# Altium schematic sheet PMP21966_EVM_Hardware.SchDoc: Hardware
size 431 x 279 mm; Date: Not shown in title block; ApprovedBy: Not shown in title block; CheckedBy: Not shown in title block; Author: Not shown in title block; CompanyName: Not shown in title block; DrawnBy: Tiger Z; Engineer: Not shown in title block; Organization: Not shown in title block; Address1: Not shown in title block; Address2: Not shown in title block; Address3: Not shown in title block; Address4: Not shown in title block; DocumentNumber: 6; Revision: Use project parameter SCH_Rev; SheetNumber: 3; SheetTotal: 3; PageSetup: Record=PageOptions¦CenterHorizontal=True¦CenterVertical=True¦PrintScale=1.00¦XCorrection=1.00¦YCorrection=1.00¦PrintKind=0¦BorderSize=5000000¦LeftOffset=0¦BottomOffset=0¦Orientation=2¦PaperLength=1000¦PaperWidth=1000¦Scale=100¦PaperSource=15¦PrintQuality=600¦MediaType=1¦DitherType=10¦PaperKind=Letter¦PrintScaleMode=1
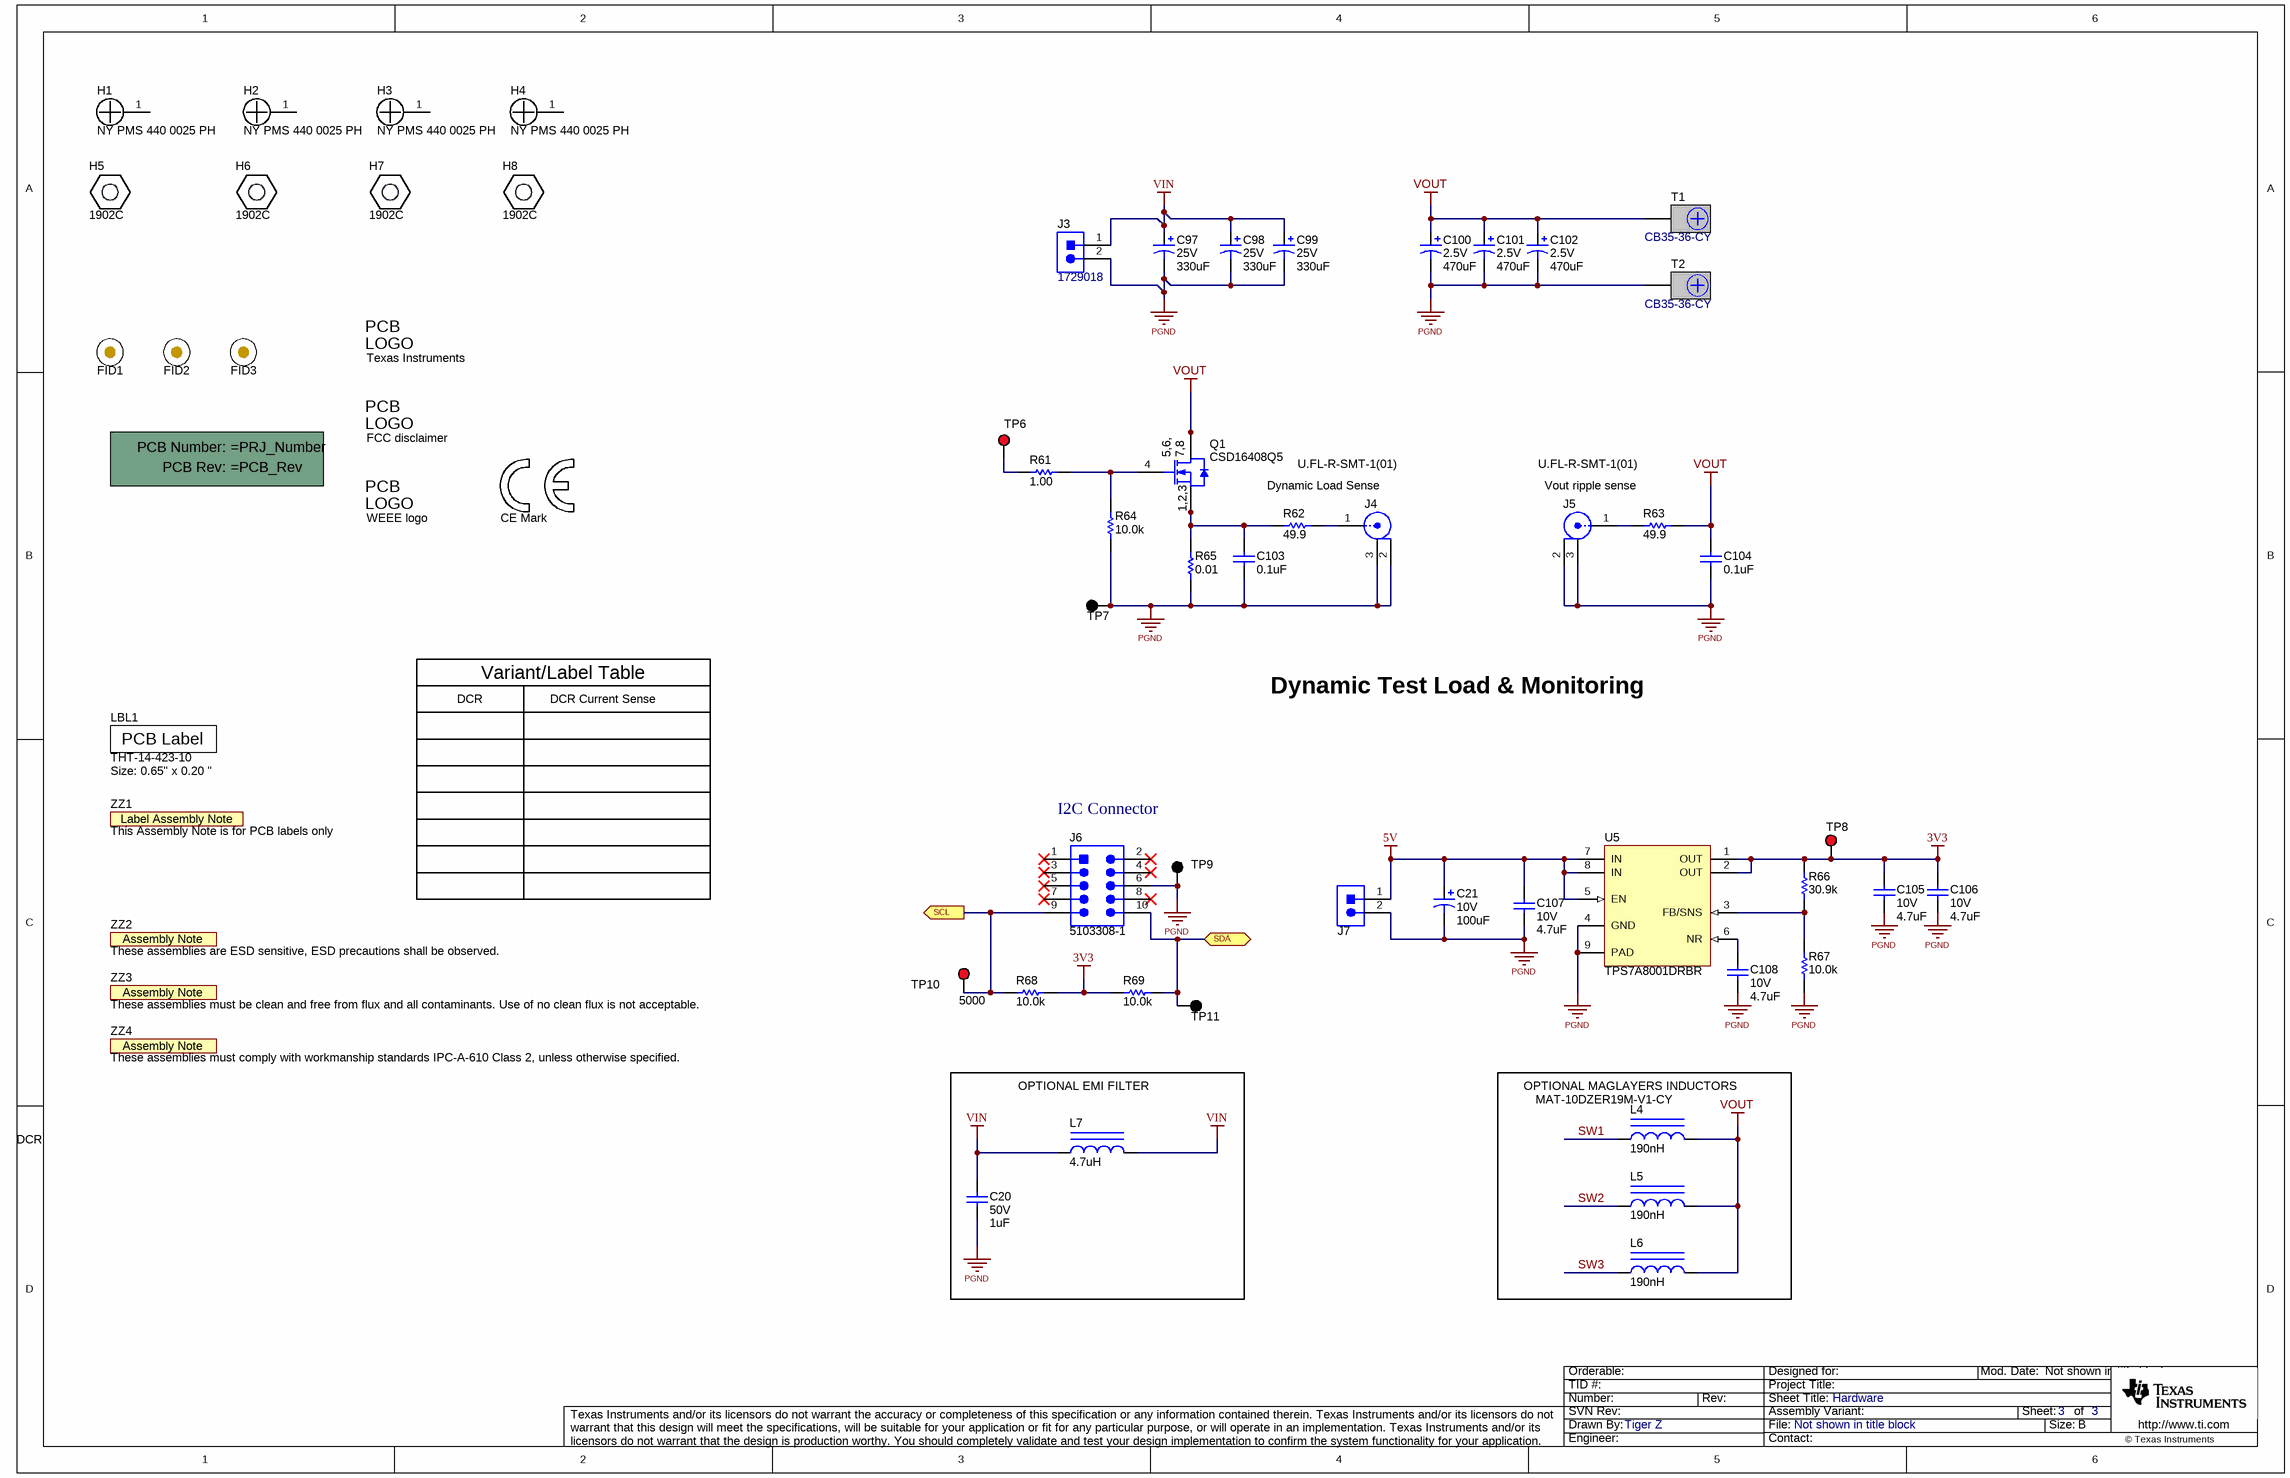
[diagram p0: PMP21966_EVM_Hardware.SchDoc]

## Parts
!PCB1  Printed Circuit Board  (value not drawn)  (mechanical)
C20  VDC_V: 50V  ValueDisplayed: 1uF  [0805_HV]  (hidden comment: C0805C105K5RACTU)
C21  VDC_V: 10V  ValueDisplayed: 100uF  [SM_RADIAL_6.3AMM]  (hidden comment: UUD1A101MCL1GS)
C97  VDC_V: 25V  ValueDisplayed: 330uF  [CAPSMT_62_HA0]  (hidden comment: EMVY250ADA331MHA0G)
C98  VDC_V: 25V  ValueDisplayed: 330uF  [CAPSMT_62_HA0]  (hidden comment: EMVY250ADA331MHA0G)
C99  VDC_V: 25V  ValueDisplayed: 330uF  [CAPSMT_62_HA0]  (hidden comment: EMVY250ADA331MHA0G)
C100  VDC_V: 2.5V  ValueDisplayed: 470uF  [GX_2TERM]  (hidden comment: EEF-GX0E471R)
C101  VDC_V: 2.5V  ValueDisplayed: 470uF  [GX_2TERM]  (hidden comment: EEF-GX0E471R)
C102  VDC_V: 2.5V  ValueDisplayed: 470uF  [GX_2TERM]  (hidden comment: EEF-GX0E471R)
C103  ValueDisplayed: 0.1uF  [0402S]  (hidden comment: CGA2B3X7R1H104K050BB)
C104  ValueDisplayed: 0.1uF  [0402S]  (hidden comment: CGA2B3X7R1H104K050BB)
C105  VDC_V: 10V  ValueDisplayed: 4.7uF  [0603S]  (hidden comment: GRM188Z71A475ME15D)
C106  VDC_V: 10V  ValueDisplayed: 4.7uF  [0603S]  (hidden comment: GRM188Z71A475ME15D)
C107  VDC_V: 10V  ValueDisplayed: 4.7uF  [0603S]  (hidden comment: GRM188Z71A475ME15D)
C108  VDC_V: 10V  ValueDisplayed: 4.7uF  [0603S]  (hidden comment: GRM188Z71A475ME15D)
FID1  Fiducial  [Fiducial10-20]  (value not drawn)
FID2  Fiducial  [Fiducial10-20]  (value not drawn)
FID3  Fiducial  [Fiducial10-20]  (value not drawn)
H1  NY PMS 440 0025 PH  [NY PMS 440 0025 PH]
H2  NY PMS 440 0025 PH  [NY PMS 440 0025 PH]
H3  NY PMS 440 0025 PH  [NY PMS 440 0025 PH]
H4  NY PMS 440 0025 PH  [NY PMS 440 0025 PH]
H5  1902C  [Keystone_1902C]
H6  1902C  [Keystone_1902C]
H7  1902C  [Keystone_1902C]
H8  1902C  [Keystone_1902C]
J3  1729018  [Phoenix_1729018]
J4  U.FL-R-SMT-1(01)  [CONN_UFL-R-SMT-1]
J5  U.FL-R-SMT-1(01)  [CONN_UFL-R-SMT-1]
J6  5103308-1  [CONN_5103308-1]
J7  HTSW-102-07-G-S  [Samtec_HTSW-102-07-G-S]  (value not drawn)
L4  ValueDisplayed: 190nH  [IHLP-4040DZ]  (hidden comment: IHLP4040DZERR19M11)
L5  ValueDisplayed: 190nH  [IHLP-4040DZ]  (hidden comment: IHLP4040DZERR19M11)
L6  ValueDisplayed: 190nH  [IHLP-4040DZ]  (hidden comment: IHLP4040DZERR19M11)
L7  ValueDisplayed: 4.7uH  [IHLP-2525AH]  (hidden comment: IHLP2525AHER4R7M01)
LBL1  THT-14-423-10  Note: Size: 0.65" x 0.20 "  [Label_650x200]
Logo1  Texas Instruments  [TI_Stacked_Overlay_Small]  (no BOM)
Logo2  FCC disclaimer  [FCC_disclaimer]  (no BOM)
Logo3  CE Mark  [CE_Mark_5mm]  (no BOM)
Logo4  WEEE logo  [WEEE_Minimum]  (no BOM)
Q1  CSD16408Q5  [DQH0008A]
R61  ValueDisplayed: 1.00  [0402S]  (hidden comment: CRCW04021R00FKED)
R62  ValueDisplayed: 49.9  [0402S]  (hidden comment: Resistor)
R63  ValueDisplayed: 49.9  [0402S]  (hidden comment: Resistor)
R64  ValueDisplayed: 10.0k  [0402S]  (hidden comment: CRCW040210K0FKED)
R65  ValueDisplayed: 0.01  [2010]  (hidden comment: CSRN2010FK10L0)
R66  ValueDisplayed: 30.9k  [0402S]  (hidden comment: CRCW040230K9FKED)
R67  ValueDisplayed: 10.0k  [0402S]  (hidden comment: CRCW040210K0FKED)
R68  ValueDisplayed: 10.0k  [0402S]  (hidden comment: CRCW040210K0FKED)
R69  ValueDisplayed: 10.0k  [0402S]  (hidden comment: CRCW040210K0FKED)
T1  CB35-36-CY  [CB35-36-CY]
T2  CB35-36-CY  [CB35-36-CY]
TP6  5000  [Keystone5000]  (value not drawn)
TP7  5001  [Keystone5001]  (value not drawn)
TP8  5000  [Keystone5000]  (value not drawn)
TP9  5001  [Keystone5001]  (value not drawn)
TP10  5000  [Keystone5000]
TP11  5001  [Keystone5001]  (value not drawn)
U5  TPS7A8001DRBR  [DRB0008A]
ZZ1  This Assembly Note is for PCB labels only  [AssemblyNoteLabel]  (no BOM)
ZZ2  These assemblies are ESD sensitive, ESD precautions shall be observed.  [AssemblyNote]  (no BOM)
ZZ3  These assemblies must be clean and free from flux and all contaminants. Use of no clean flux is not acceptable.  [AssemblyNote]  (no BOM)
ZZ4  These assemblies must comply with workmanship standards IPC-A-610 Class 2, unless otherwise specified.  [AssemblyNote]  (no BOM)

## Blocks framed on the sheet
OPTIONAL EMI FILTER: C20 L7

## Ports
SCL (out), SDA (bidir)

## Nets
3V3: C105.1 C106.1 R66.2 R68.2 R69.1 TP8.1 U5.1(OUT) U5.2(OUT)
5V: C21.1(+) C107.1 J7.1 U5.5(EN) U5.7(IN) U5.8(IN)
PGND: C20.1 C21.2(-) C97.2(-) C98.2(-) C99.2(-) C100.2(-) C101.2(-) C102.2(-) C103.1 C104.1 C105.2 C106.2 C107.2 C108.2 J3.2 J4.2 J4.3 J5.2 J5.3 J6.6 J7.2 R64.1 R65.1 R67.1 T2.1 TP7.1 TP9.1 U5.4(GND) U5.9(PAD)
VIN: C20.2 C97.1(+) C98.1(+) C99.1(+) J3.1 L7.1 L7.2
VOUT: C100.1(+) C101.1(+) C102.1(+) C104.2 L4.2 L5.2 L6.2 Q1.5(D) Q1.6(D) Q1.7(D) Q1.8(D) Q1.9(D) R63.2 T1.1
SCL: J6.9 R68.1 TP10.1 ; port SCL
SDA: J6.10 R69.2 TP11.1 ; port SDA
SW1: L4.1
SW2: L5.1
SW3: L6.1
NetC103_2: C103.2 Q1.1(S) Q1.2(S) Q1.3(S) R62.1 R65.2
NetC108_1: C108.1 U5.6(NR)
NetJ4_1: J4.1 R62.2
NetJ5_1: J5.1 R63.1
NetQ1_4: Q1.4(G) R61.2 R64.2
NetR61_1: R61.1 TP6.1
NetR66_1: R66.1 R67.2 U5.3(FB/SNS)

Not connected (* = marked no-connect by the designer): H1 1; H2 1; H3 1; H4 1; J6 1* 2* 3* 4* 5* 7* 8*

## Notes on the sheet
- Dynamic Load Sense
- Vout ripple sense
- DCR
- Variant/Label Table
- DCR Current Sense
- Dynamic Test Load & Monitoring
- I2C Connector
- (near L4) MAT-10DZER19M-V1-CY
- (near L4) OPTIONAL MAGLAYERS INDUCTORS

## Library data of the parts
!PCB1 = CMP-0003618-2: Manufacturer: Any
C20 = CMP-0007730-2: CAP, CERM, 1 uF, 50 V, +/- 10%, X7R, 0805; Manufacturer: Kemet; TaMin_C: -55°C; Polarized: N; SizeAreaWB_mm2: 6.75; Value1: Unknown; U/M: EA; Value: 1uF; TaMax_C: 125°C; SizeZ_mm: 1.45; SizeX_mm: 2; SizeY_mm: 1.25; Cap_Case: 0805; SizeArea_mm2: 2.5; Cap_F: 1µF; AEC Category: Q200
C21 = CMP-0011108-1: CAP, AL, 100 uF, 10 V, +/- 20%, 0.44 ohm, SMD; Manufacturer: Nichicon; TaMin_C: -55°C; ESR_ohm: 0.44; Polarized: Y; SizeAreaWB_mm2: 79.98; U/M: EA; Value: 100uF; TaMax_C: 105°C; SizeZ_mm: 6; SizeX_mm: 7.3; SizeY_mm: 6.6; Cap_Case: 6.3x5.8; SizeArea_mm2: 48.18; CompType: Capacitor; Cap_F: 100µF; IRMS_A: 230mA; AEC Category: Q200
C97-C99 = CMP-0010995-1: CAP, AL, 330 uF, 25 V, +/- 20%, 0.3 ohm, SMD; Manufacturer: Chemi-Con; TaMin_C: -55°C; ESR_ohm: 0.3; Polarized: Y; SizeAreaWB_mm2: 106.09; Value1: 0.3 ohm; U/M: EA; Value: 330uF; TaMax_C: 105°C; SizeZ_mm: 10; SizeX_mm: 8.3; Cap_Case: HA0; SizeArea_mm2: 68.89; CompType: Capacitor; Cap_F: 330µF; IRMS_A: 450mA; AEC Category: Q200
C100-C102 = CMP-0012242-3: CAP, Aluminum Polymer, 470 uF, 2.5 V, +/- 20%, 0.003 ohm, SMD_7.3x1.9x4.3mm SMD; Manufacturer: Panasonic; TaMin_C: -40°C; ESR_ohm: 3m; Polarized: Y; Value: 470uF; TaMax_C: 105°C; CompType: Capacitor; AEC Qualified: N; Cap_F: 470µF; IRMS_A: 10.2A; AEC Category: Q200
C103 C104 = CMP-0006325-2: CAP, CERM, 0.1 uF, 50 V, +/- 10%, X7R, AEC-Q200 Grade 1, 0402; Manufacturer: TDK; TaMin_C: -55°C; ESR_ohm: 0.039064; Polarized: N; SizeAreaWB_mm2: 3; Value1: 0.039064 ohm; U/M: EA; Value: 0.1uF; TaMax_C: 125°C; SizeZ_mm: 0.6; SizeX_mm: 1; SizeY_mm: 0.5; Cap_Case: 0402; Value2: 50V; CompType: Capacitor; AEC Qualified: Y; Cap_F: 100nF; IRMS_A: 8.14669dA; AEC Category: Q200
C105-C108 = CMP-0007498-4: CAP, CERM, 4.7 uF, 10 V, +/- 20%, X7R, 0603; Manufacturer: MuRata; TaMin_C: -55°C; Polarized: N; SizeAreaWB_mm2: 4.68; Value1: Unknown; U/M: EA; Value: 4.7uF; TaMax_C: 125°C; SizeZ_mm: 1; SizeX_mm: 1.6; SizeY_mm: 0.8; Cap_Case: 0603; SizeArea_mm2: 1.28; CompType: Capacitor; Cap_F: 4.7µF; AEC Category: Q200
FID1-FID3 = CMP-0077181-1: Fiducial mark.  There is nothing to buy or mount.
H1-H4 = CMP-0003617-1: Machine Screw, Round, #4-40 x 1/4, Nylon, Philips panhead; Manufacturer: B&F Fastener Supply; CompType: Hardware
H5-H8 = CMP-0003610-1: Standoff, Hex, 0.5"L #4-40 Nylon; Manufacturer: Keystone; CompType: Hardware
J3 = CMP-0055486-1: TERM BLOCK 2POS 5mm, TH; Manufacturer: Phoenix Contact; CT: TRUE; Green_REACh: Incomplete; CompType: Terminal Block; CNHeader: FALSE; Green_Lifecycle: Not Set
J4 J5 = CMP-0075320-1: Receptacle, Ultra Miniature Coaxial, Male Pin, 50 ohm, SMT; Manufacturer: Hirose Electric Co. Ltd.; CNHeader: False; Gender: Female; ContactFinish: Gold
J6 = CMP-0054834-2: Header (shrouded), 100mil, 5x2, Gold, TH; Manufacturer: TE Connectivity; Green_Lifecycle: Active; Green_REACh: Passed
J7 = CMP-0075483-1: Header, 100mil, 2x1, Gold, TH; Manufacturer: Samtec; Green_REACh: Passed; CT: False; Green_Lifecycle: Active; CNHeader: True
L4-L6 = CMP-0063459-1: Inductor, Shielded, Powdered Iron, 190 nH, 40 A, 0.0008 ohm, SMD; Manufacturer: Vishay-Dale; Isat: 46A @ 20% inductance drop; Irms: 40A @ 40C rise; Green_Lifecycle: Active; SizeAreaWB_mm2: 166.05; DCR_ohm: 800µ; Green_REACh: Passed; Value: 190nH; Imax_A: 40A; SizeZ_mm: 4; SizeX_mm: 11.5; SizeY_mm: 10.3; SizeArea_mm2: 118.45; AEC Category: Q200
L7 = CMP-0063348-1: Inductor, Shielded, Ferrite, 4.7 uH, 3 A, 0.078 ohm, SMD; Manufacturer: Vishay-Dale; Isat: 8A @ 20% inductance drop; Irms: 3A @ 40C rise; Green_Lifecycle: Active; SizeAreaWB_mm2: 75.0442; DCR_ohm: 0.078; Green_REACh: Passed; Value: 4.7uH; Imax_A: 3A; SizeZ_mm: 1.8; SizeX_mm: 6.86; SizeY_mm: 6.47; SizeArea_mm2: 44.3842; Ind_H: 4.7µH; AEC Category: Q200
LBL1 = CMP-0003625-1: Thermal Transfer Printable Labels, 0.650" W x 0.200" H - 10,000 per roll; Manufacturer: Brady; CompType: Label
Logo1 = CMP-0074838-1: Texas Instrument Corporate Signature; SymbolCreator: a0412235; Lib Reference: TI_Logo; Library Reference: Logo
Logo2 = CMP-0074847-1: FCC_disclaimer; Library Reference: Logo
Logo3 = CMP-0074844-1: SymbolCreator: a0412235
Logo4 = CMP-0074769-1
Q1 = CMP-0000264-1: MOSFET, N-CH, 25 V, 113 A, DQH0008A (VSON-CLIP-8); Manufacturer: Texas Instruments; Alternate Manufacturer: None; U/M: EA; ChType: N; Value: 25V; Value1: 0.005; Rdson45_ohm: 5.4m; Value2: 6.7 nC; QgTyp_nC: 6.7; Vgs_V: 16V; IdsMax_A: 113A; SizeAreaWB_mm2: 56; SizeArea_mm2: 30; SizeX_mm: 6; SizeY_mm: 5; SizeZ_mm: 1.05; AEC Category: Q101
R61 = CMP-0026129-2: RES, 1.00, 1%, 0.063 W, AEC-Q200 Grade 0, 0402; Manufacturer: Vishay-Dale; Power_W: 63mW; TempCo: 100 ppm/C; Value_Code: 1R00; Value: 1.00; EIA_Code: E96; Res_ohm: 1; SizeY_mm: 0.5; SizeZ_mm: 0.6; Value2: 0.063W; AEC Qualified: Y; VDC_V: 50V; AEC Category: Q200; AEC Grade: 0
R62 R63 = CMP-0026404-2: RES, 49.9, 1%, 0.063 W, AEC-Q200 Grade 0, 0402; PartNumber: CRCW040249R9FKED; Manufacturer: Vishay-Dale; Value: 49.9; Value_Code: 49R9; Power_W: 63mW; Value2: 0.063W; VDC_V: 50V; TempCo: 100 ppm/C; EIA_Code: E96; SizeArea_mm2: 0.5; SizeX_mm: 1; SizeZ_mm: 0.6; AEC Category: Q200; AEC Qualified: Y; AEC Grade: 0
R64 = CMP-0025958-3: RES, 10.0 k, 1%, 0.063 W, AEC-Q200 Grade 0, 0402; Manufacturer: Vishay-Dale; Value: 10.0k; Res_ohm: 10k; Value_Code: 10k0; Power_W: 63mW; Value2: 0.063W; VDC_V: 50V; TempCo: 100 ppm/C; SizeArea_mm2: 0.5; SizeX_mm: 1; SizeZ_mm: 0.6; EIA_Code: E96; AEC Category: Q200; AEC Qualified: Y; AEC Grade: 0
R65 = CMP-0016514-2: RES, 0.01, 1%, 1 W, 2010; Manufacturer: Stackpole Electronics Inc; Value: 0.01; Value_Code: R010; Power_W: 1W; TempCo: 250 ppm/C; SizeArea_mm2: 12.5; SizeX_mm: 5; SizeY_mm: 2.5; SizeZ_mm: 1.66; EIA_Code: E96; U/M: EA; AEC Category: Q200
R66 = CMP-0026285-2: RES, 30.9 k, 1%, 0.063 W, AEC-Q200 Grade 0, 0402; Manufacturer: Vishay-Dale; Power_W: 63mW; TempCo: 100 ppm/C; Value_Code: 30k9; Value: 30.9k; EIA_Code: E96; SizeX_mm: 1; SizeY_mm: 0.5; SizeZ_mm: 0.6; Value2: 0.063W; AEC Qualified: Y; VDC_V: 50V; AEC Category: Q200; AEC Grade: 0
R67 = CMP-0025958-3: RES, 10.0 k, 1%, 0.063 W, AEC-Q200 Grade 0, 0402; Manufacturer: Vishay-Dale; Power_W: 63mW; TempCo: 100 ppm/C; Value_Code: 10k0; Value: 10.0k; EIA_Code: E96; Res_ohm: 10k; SizeX_mm: 1; SizeY_mm: 0.5; SizeZ_mm: 0.6; Value2: 0.063W; AEC Qualified: Y; VDC_V: 50V; AEC Category: Q200; AEC Grade: 0
R68 R69 = CMP-0025958-3: RES, 10.0 k, 1%, 0.063 W, AEC-Q200 Grade 0, 0402; Manufacturer: Vishay-Dale; Power_W: 63mW; TempCo: 100 ppm/C; Value_Code: 10k0; Value: 10.0k; EIA_Code: E96; Res_ohm: 10k; SizeX_mm: 1; SizeY_mm: 0.5; SizeZ_mm: 0.6; Value2: 0.063W; CompType: Resistor; AEC Qualified: Y; VDC_V: 50V; AEC Category: Q200; AEC Grade: 0
T1 T2 = CMP-0055442-1: Terminal 50A Lug; Manufacturer: Panduit; CNHeader: FALSE; Green_Lifecycle: Not Set; Cert_CULUS: Y; Green_REACh: Incomplete; Voltage_V: 600V; CompType: Screw Terminal; ContactFinish: Copper
TP6 = CMP-0055137-1: Test Point, Miniature, Red, TH; Manufacturer: Keystone; CNHeader: FALSE; ContactFinish: Silver; CT: TRUE; Green_Lifecycle: Active; Green_REACh: Passed
TP7 TP11 = CMP-0055138-1: Test Point, Miniature, Black, TH; Manufacturer: Keystone; CNHeader: FALSE; ContactFinish: Silver; CT: TRUE; Green_Lifecycle: Active; Green_REACh: Passed
TP8 TP10 = CMP-0055137-1: Test Point, Miniature, Red, TH; Manufacturer: Keystone; CNHeader: FALSE; Green_Lifecycle: Active; Green_REACh: Passed; ContactFinish: Silver; CT: TRUE
TP9 = CMP-0055138-1: Test Point, Miniature, Black, TH; Manufacturer: Keystone; CNHeader: FALSE; Green_Lifecycle: Active; Green_REACh: Passed; ContactFinish: Silver; CT: TRUE
U5 = CMP-0036419-3: Low-Noise, High-Bandwidth PSRR, 1A Low-Dropout (LDO) Linear Regulator, DRB0008A (VSON-8); Manufacturer: Texas Instruments; Vdo(Typ)(mV): 170; Accuracy(%): 3; Iout(Max)(A): 1; Vin(Min)(V): 2.2; Vin(Max)(V): 6.5; Vout Adj(Max)(V): 6; Vout Adj(Min)(V): 0.8; Iq(Typ)(mA): 0.04; Green_Lifecycle: Active; AEC Category: Q200; SizeX_mm: 3.0; Green_REACh: Passed; Rating: Catalog; AEC Qualified: N; CompType: IC; SizeArea_mm2: 9.0; SizeZ_mm: 1.0; SizeAreaWB_mm2: 16.0
ZZ1 = CMP-0003616-3
ZZ2 = CMP-0077236-1
ZZ3 = CMP-0077237-1
ZZ4 = CMP-0077238-1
